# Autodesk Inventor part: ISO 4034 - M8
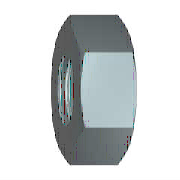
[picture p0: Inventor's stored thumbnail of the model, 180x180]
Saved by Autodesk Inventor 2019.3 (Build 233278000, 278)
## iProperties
Created: 2018-01
Part Number: ISO 4034 - M8
Material: Ocel
Description: Šestihranné matice. Výrobní řada C
Document SubType Name: Modeling
Standard: ISO 4034
Designer: B-hon
Standards Organization: CSN
Language: cs-CZ
Size Designation: M8
Categories: <MemberInstance><Categories><Category DisplayName="Spojovací materiál" InternalName="e4da775c-781d-43d5-af7c-5136215cf5a6" Mnemonic="FSTN"><Category DisplayName
Density: 7.85 g/cm^3
Appearance: Plech
IsCustomPart: 0
Author: B-hon
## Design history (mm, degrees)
sketch "Náčrt1"
  geometry: L1 (-7.506, 0)-(-3.753, 6.5); L2 (-3.753, 6.5)-(3.753, 6.5); L3 (3.753, 6.5)-(7.506, 0); L4 (7.506, 0)-(3.753, -6.5); L5 (3.753, -6.5)-(-3.753, -6.5); L6 (-3.753, -6.5)-(-7.506, 0); 2 further points
  constraints: 12 end point, 1 coincident, 1 horizontal, 11 other
  dimensions: "d0" = 15.01111 distance of L3.end L1.start (= 1.1547 x SW)
extrude "Těleso" new body sketch "Náčrt1" distance "d1" = 7.9 (= KOH); taper "d2" = 0 deg
sketch "Náčrt2"
  geometry: L1 (0, 3.753)-(0, 7.506) reference; L2 (0, 7.506)-(7.9, 7.506) reference; L3 (7.9, 3.753)-(7.9, 7.506) reference; L4 (-1.58, 0)-(9.48, 0) reference; L5 (0.581, 7.506)-(0, 6.5); L6 (7.319, 7.506)-(7.9, 6.5)
  constraints: 4 end point, 4 point on line
  dimensions: "d3" = 30 deg angle of L1 L5 (= ANG1); "d4" = 30 deg angle of L3 L6 (= ANG2); "d5" = 13 diameter of L5.end L4 (= SW0); "d6" = 13 diameter of L6.end L4 (= SW01)
revolve "Zkosení1" sketch "Náčrt2" stored, may be unused: angle "d7" = 90 deg
sketch "Náčrt3"
  geometry: A1 r 6.5 centre (0, 0) between (-3.25, -5.629) and (3.25, -5.629) reference; 1 further point
  constraints: 1 coincident
hole "Závit" sketch "Náčrt3" at (0, 0) diameter "d25" = 6.647; stored, may be unused: countersink angle "d29" = 82 deg, drill point angle "d31" = 118 deg; dims "d26" = 6, "d27" = 4, "d28" = 2, "d30" = 8
workaxis "Work Axis1"
workplane "Work Plane1"
body "Solid1"
chamfer "Zkosení2" distance "d8" = 0.67658 (= -0.5 x GD1 + 0.5 x NND); stored, may be unused: angle "d9" = 30 deg, second distance "d40" = 0.67658 (= -0.5 x GD1 + 0.5 x NND)
chamfer "Zkosení3" distance "d10" = 0.67658 (= -0.5 x GD1 + 0.5 x NND); stored, may be unused: angle "d11" = 30 deg, second distance "d41" = 0.67658 (= -0.5 x GD1 + 0.5 x NND)
other parameters: "ANG1" = 30 deg [user parameter; used in 1 equation term], "ANG2" = 30 deg [user parameter; used in 1 equation term], "NND" = 8 [user parameter; used in 4 equation terms], "KOH" = 7.9 [user parameter; used in 1 equation term], "SW" = 13 [user parameter; used in 4 equation terms], "SW0" = 13 (= SW) [user parameter; used in 1 equation term], "SW01" = 13 (= SW) [user parameter; used in 1 equation term], "GD1" = 6.64684 (computed from THREADDIA, PTC, TOA) [user parameter; used in 4 equation terms], "d13" = 0, "d14" = 0, "d39" = 0, "d42" = 0, "GUL" = 0.67658 (= 0.541266 x PTC) [user parameter], "TPU" = 8 (computed from PTC) [user parameter], "THREADDIA" = 8 [user parameter; used in 1 equation term], "TOA" = 30 deg [user parameter; used in 1 equation term], "PTC" = 1.25 [user parameter; used in 4 equation terms], "E0" = 15.015 (= 1.155 x SW) [user parameter], "GAL" = 0.67658 (= 0.541266 x PTC) [user parameter]
